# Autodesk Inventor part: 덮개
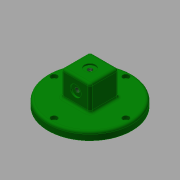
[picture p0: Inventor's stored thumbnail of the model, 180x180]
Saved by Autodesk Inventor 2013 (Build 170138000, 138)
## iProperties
Created: 2017-08
Part Number: 덮개
Material: 알루미늄 6061
Document SubType Name: Modeling
Designer: mduedu
Density: 1 g/cm^3
Author: mduedu
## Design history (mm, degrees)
sketch "스케치1"
  geometry: C1 r 52.5 at (0, 0); 1 further point
  constraints: 1 centre point, 1 coincident
  dimensions: "d55" = 105 diameter of C1
extrude "돌출1" new body sketch "스케치1" distance "d5" = 10; taper "d6" = 0 deg
sketch "스케치2"
  geometry: L1 (-18, -18)-(18, -18); L2 (18, -18)-(18, 18); L3 (18, 18)-(-18, 18); L4 (-18, 18)-(-18, -18); L5 (-18, -18)-(18, 18); L6 (18, -18)-(-18, 18); 1 further point
  constraints: 12 end point, 2 midpoint, 2 parallel, 2 perpendicular, 1 horizontal
  dimensions: "d7" = 36 distance of L2.end L3.end
extrude "돌출2" join sketch "스케치2" distance "d9" = 32; taper "d10" = 0 deg
sketch "스케치3"
  geometry: C1 r 37 at (0, 0); 1 further point
  constraints: 1 centre point, 1 coincident
  dimensions: "d56" = 74 diameter of C1
extrude "돌출3" join sketch "스케치3" distance "d12" = 6; taper "d13" = 0 deg
sketch "스케치4"
  geometry: C1 r 33 at (0, 0); 1 further point
  constraints: 1 centre point, 1 coincident
  dimensions: "d57" = 66 diameter of C1
extrude "돌출4" cut sketch "스케치4" distance "d16" = 5; taper "d17" = 0 deg
sketch "스케치5"
  geometry: C1 r 9 at (0, 0); 1 further point
  constraints: 1 centre point, 1 coincident
  dimensions: "d18" = 18 diameter of C1
extrude "돌출5" cut sketch "스케치5" distance "d19" = 34; taper "d20" = 0 deg
sketch "스케치6"
  geometry: 2 further points
  constraints: 1 coincident
hole "구멍1" sketch "스케치6" at (0, 0) diameter "d21" = 5.917; stored, may be unused: countersink angle "d25" = 90 deg, drill point angle "d27" = 118 deg; dims "d22" = 6, "d23" = 14, "d24" = 2, "d26" = 8
sketch "스케치7"
  geometry: L1 (-34.5, -10)-(70.5, -10) reference; 3 further points
  constraints: 1 midpoint, 1 vertical alignment
  dimensions: "d58" = 26 distance from line of point (18, 16) L1
hole "구멍2" sketch "스케치7" at (18, 16) diameter "d29" = 5.917; stored, may be unused: countersink angle "d33" = 90 deg, drill point angle "d35" = 118 deg; dims "d30" = 6, "d31" = 14, "d32" = 2, "d34" = 8
fillet "모깎기2" dims "d37" = 3
fillet "모깎기3" dims "d38" = 3
fillet "모깎기4" dims "d39" = 3
fillet "모깎기5" dims "d40" = 3
chamfer "모따기1" distance "d41" = 1; stored, may be unused: second distance "d42" = 2, angle "d43" = 45 deg
fillet "모깎기7" dims "d45" = 3
fillet "모깎기8" dims "d46" = 3
sketch "스케치10" dims "d59" = 90
  geometry: 3 further points
  constraints: 2 vertical alignment, 1 coincident, 2 other
hole "구멍4" sketch "스케치10" at (0, 45) diameter "d60" = 4.5; stored, may be unused: countersink angle "d64" = 90 deg, drill point angle "d66" = 118 deg; dims "d61" = 6, "d62" = 8, "d63" = 4.6, "d65" = 8
node "솔리드1"
pattern_circular "원형 패턴1" dims angle "d68" = 360 deg
